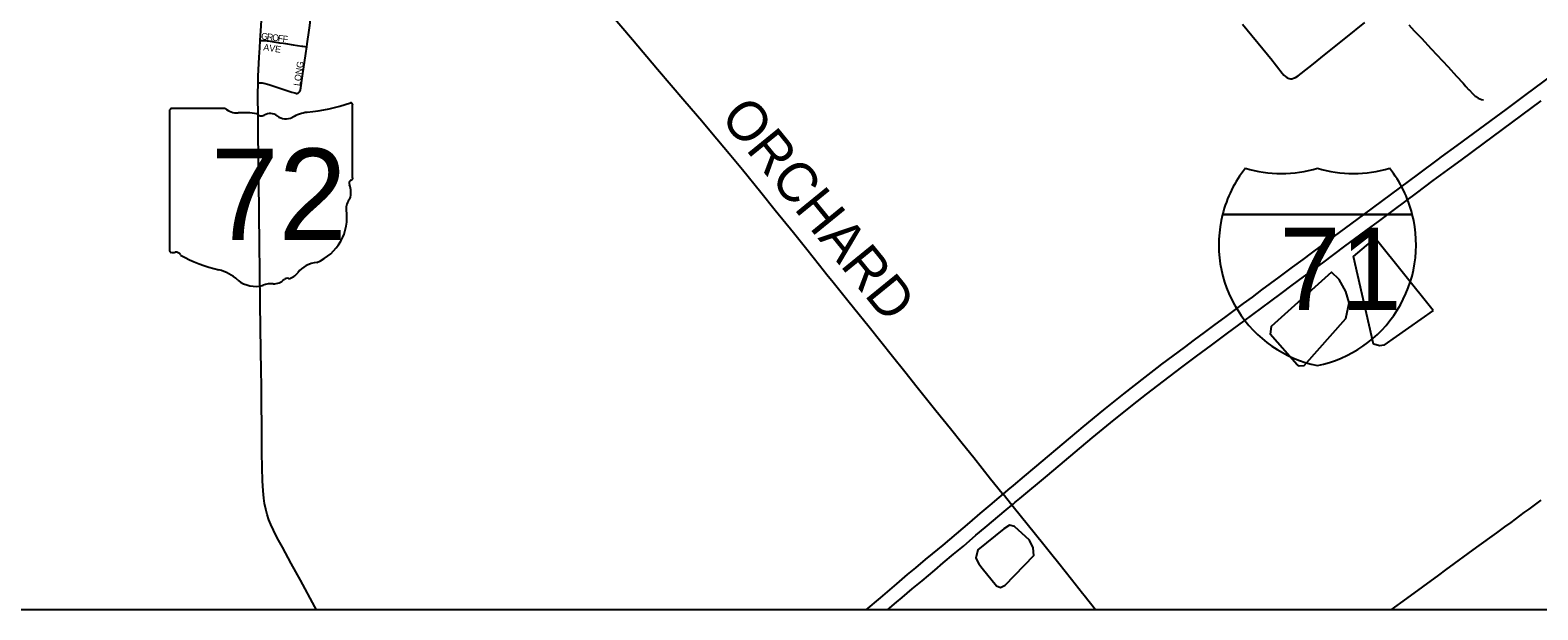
# Model space of a CAD drawing. Extents: x -49 to -8.2, y 9.4 to 23.5.
# Drawn here: x -12.253 to -11.168, y 9.409 to 9.826 of the extents above; entities that cross this region are included whole.
import ezdxf

# ---------------------------------------------------------------- set-up
doc = ezdxf.new("R2010")
doc.units = 0
for name, color, linetype in [('GM_X_Adjacent_County', 7, 'Continuous'), ('GM_X_County_Road', 7, 'Continuous'), ('GM_X_County_Road_Text', 7, 'Continuous'), ('GM_X_Interstate_Route', 7, 'Continuous'), ('GM_X_Interstate_Shield', 7, 'Continuous'), ('GM_X_Minor_Lake', 7, 'Continuous'), ('GM_X_State_Route', 7, 'Continuous'), ('GM_X_State_Shield', 7, 'Continuous'), ('GM_X_Township_Road', 7, 'Continuous'), ('GM_X_Township_Subdivision', 7, 'Continuous'), ('GM_X_Township_Subdivision_Text', 7, 'Continuous')]:
    doc.layers.add(name, color=color, linetype=linetype)

msp = doc.modelspace()

# ---------------------------------------------------------------- linework, layer by layer
at = {"layer": 'GM_X_Adjacent_County'}
msp.add_lwpolyline([(-14.9662, 16.2087), (-8.1662, 16.2087), (-8.1662, 9.4087), (-14.9662, 9.4087)], close=True, dxfattribs=at)
at = {"layer": 'GM_X_County_Road'}
for points in [[(-11.6146, 9.5686), (-11.6235, 9.5799), (-11.6324, 9.591), (-11.6493, 9.6121), (-11.6604, 9.626), (-11.6645, 9.631), (-11.6751, 9.6443), (-11.6796, 9.6498), (-11.6849, 9.6565), (-11.6942, 9.6681), (-11.7038, 9.68), (-11.7168, 9.6962), (-11.7272, 9.7091), (-11.7404, 9.7253), (-11.75, 9.7369), (-11.7628, 9.7521), (-11.7698, 9.7604), (-11.7819, 9.7745), (-11.8016, 9.7975), (-11.8197, 9.819), (-11.8462, 9.8503)], [(-11.4944, 9.419), (-11.4956, 9.4205), (-11.5035, 9.4305), (-11.5126, 9.4419), (-11.5186, 9.4494), (-11.5235, 9.4555), (-11.5354, 9.4702), (-11.5446, 9.4815), (-11.5465, 9.4839), (-11.5528, 9.4918), (-11.5533, 9.4924), (-11.5617, 9.5028), (-11.5739, 9.5181), (-11.5823, 9.5285), (-11.5907, 9.5389), (-11.6012, 9.552), (-11.6136, 9.5675), (-11.6146, 9.5686)], [(-11.4861, 9.4087), (-11.4944, 9.419)]]:
    msp.add_lwpolyline(points, dxfattribs=at)
at = {"layer": 'GM_X_Interstate_Route'}
for points in [[(-11.6513, 9.4087), (-11.6411, 9.4173), (-11.6359, 9.4217), (-11.6293, 9.4273), (-11.6215, 9.434), (-11.6155, 9.439), (-11.6086, 9.4448), (-11.6036, 9.449), (-11.596, 9.4553), (-11.5768, 9.4716), (-11.5692, 9.478), (-11.5621, 9.4841), (-11.5556, 9.4894), (-11.5528, 9.4918), (-11.549, 9.495), (-11.5452, 9.4982), (-11.5373, 9.5048), (-11.5299, 9.511), (-11.5041, 9.5328), (-11.495, 9.5404), (-11.4801, 9.5526), (-11.4659, 9.5641), (-11.4505, 9.5762), (-11.4418, 9.5828), (-11.4384, 9.5854), (-11.4222, 9.5975), (-11.415, 9.6029), (-11.4078, 9.6083), (-11.4, 9.614), (-11.393, 9.6192), (-11.3795, 9.6291), (-11.3732, 9.6337), (-11.3663, 9.6389), (-11.3538, 9.6482), (-11.3443, 9.6552), (-11.3366, 9.6609), (-11.3306, 9.6653), (-11.3231, 9.6709), (-11.2931, 9.6931), (-11.2534, 9.7224), (-11.2392, 9.733), (-11.237, 9.7347), (-11.2257, 9.7429), (-11.1977, 9.7636), (-11.1905, 9.7689), (-11.177, 9.7789), (-11.1418, 9.8051)], [(-11.636, 9.4087), (-11.6296, 9.4141), (-11.6255, 9.4175), (-11.6182, 9.4237), (-11.611, 9.4296), (-11.602, 9.4372), (-11.5958, 9.4424), (-11.5885, 9.4487), (-11.5813, 9.4546), (-11.5723, 9.4623), (-11.5656, 9.4679), (-11.5505, 9.4807), (-11.5465, 9.4839), (-11.5452, 9.485), (-11.5442, 9.4858), (-11.5406, 9.4888), (-11.5208, 9.5053), (-11.4885, 9.5325), (-11.4753, 9.5433), (-11.4595, 9.556), (-11.4495, 9.5639), (-11.4372, 9.5733), (-11.4241, 9.5833), (-11.4134, 9.5913), (-11.4027, 9.5992), (-11.3912, 9.6077), (-11.3794, 9.6164), (-11.36, 9.6308), (-11.3525, 9.6364), (-11.3445, 9.6423), (-11.3363, 9.6484), (-11.3225, 9.6585), (-11.3065, 9.6704), (-11.2958, 9.6783), (-11.2903, 9.6824), (-11.2823, 9.6883), (-11.2708, 9.6968), (-11.2549, 9.7087), (-11.2429, 9.7176), (-11.2324, 9.7253), (-11.2299, 9.7272), (-11.2229, 9.7323), (-11.2069, 9.7442), (-11.1652, 9.775)]]:
    msp.add_lwpolyline(points, dxfattribs=at)
at = {"layer": 'GM_X_Interstate_Shield'}
for p, q in [((-11.3947, 9.6933), (-11.2581, 9.6933)), ((-11.2581, 9.6933), (-11.3947, 9.6933)), ((-11.2581, 9.6933), (-11.3947, 9.6933))]:
    msp.add_line(p, q, dxfattribs=at)
for centre, start, end in [((-11.3086, 9.6715), 141.669, 165.8066), ((-11.3523, 9.8115), 253.0091, 286.9909), ((-11.3004, 9.8115), 253.0091, 286.9909), ((-11.3441, 9.6715), 14.1934, 38.331), ((-11.3086, 9.6715), 165.8066, 258.463), ((-11.3441, 9.6715), 281.537, 14.1934)]:
    msp.add_arc(centre, 0.0888, start, end, dxfattribs=at)
at = {"layer": 'GM_X_Minor_Lake'}
for points in [[(-11.2429, 9.6241), (-11.2785, 9.5992), (-11.2814, 9.5986), (-11.286, 9.6), (-11.3003, 9.6631), (-11.2848, 9.6761)], [(-11.2429, 9.6241), (-11.2848, 9.6761)], [(-11.3409, 9.5849), (-11.3396, 9.5843), (-11.3358, 9.5846), (-11.3058, 9.6183), (-11.3035, 9.6297), (-11.3059, 9.6379), (-11.3108, 9.6465), (-11.3161, 9.6517), (-11.3597, 9.6127), (-11.3605, 9.607)], [(-11.3409, 9.5849), (-11.3605, 9.607)], [(-11.5574, 9.4259), (-11.5545, 9.4247), (-11.5513, 9.4264), (-11.5307, 9.4478), (-11.531, 9.4533), (-11.5338, 9.4589), (-11.5445, 9.4687), (-11.5481, 9.4695), (-11.5522, 9.4669), (-11.571, 9.4519), (-11.5724, 9.4458), (-11.5703, 9.4418), (-11.5679, 9.4387)], [(-11.5679, 9.4387), (-11.5574, 9.4259)]]:
    msp.add_lwpolyline(points, dxfattribs=at)
at = {"layer": 'GM_X_State_Route'}
for points in [[(-12.0884, 9.8066), (-12.088, 9.8133), (-12.0877, 9.8186), (-12.087, 9.8291), (-12.0861, 9.8449), (-12.0852, 9.8578), (-12.0848, 9.862), (-12.0844, 9.8659)], [(-12.0473, 9.4087), (-12.0485, 9.4108), (-12.0588, 9.43), (-12.0655, 9.4421), (-12.0718, 9.4537), (-12.0755, 9.4605), (-12.0783, 9.4659), (-12.0802, 9.4701), (-12.0816, 9.4735), (-12.0828, 9.4773), (-12.0838, 9.4812), (-12.0846, 9.4851), (-12.0852, 9.4891), (-12.0857, 9.4943), (-12.0861, 9.5015), (-12.0864, 9.5111), (-12.0865, 9.5217), (-12.0866, 9.5387), (-12.0868, 9.5592), (-12.0869, 9.5701), (-12.0871, 9.5807), (-12.0872, 9.5953), (-12.0877, 9.6288), (-12.088, 9.6531), (-12.0882, 9.6708), (-12.0884, 9.6947), (-12.0888, 9.7171), (-12.0889, 9.7366), (-12.0892, 9.749), (-12.0893, 9.763), (-12.0894, 9.7796), (-12.0893, 9.7881), (-12.0892, 9.7928), (-12.0884, 9.8066)]]:
    msp.add_lwpolyline(points, dxfattribs=at)
at = {"layer": 'GM_X_State_Shield'}
for p, q in [((-12.153, 9.7678), (-12.153, 9.6677)), ((-12.1131, 9.7695), (-12.1517, 9.7695)), ((-12.0212, 9.7196), (-12.0212, 9.772)), ((-12.0212, 9.7197), (-12.0212, 9.7196))]:
    msp.add_line(p, q, dxfattribs=at)
for centre, radius, start, end in [((-12.0681, 9.9059), 0.1398, 275.8445, 288.9065), ((-12.0226, 9.7722), 0.00147, 351.8621, 97.738), ((-12.1515, 9.768), 0.00153, 98.1301, 188.1301), ((-12.1039, 9.7811), 0.0148, 231.6195, 271.1119), ((-12.099, 9.7133), 0.0532, 80.4867, 94.9883), ((-12.0869, 9.7685), 0.00427, 219.7921, 297.1024), ((-12.0806, 9.757), 0.00889, 54.4667, 119.1411), ((-12.0692, 9.7728), 0.0107, 233.8562, 294.8282), ((-12.0503, 9.7389), 0.0281, 97.3462, 120.7689), ((-12.0227, 9.7194), 0.00157, 289.6038, 7.7341), ((-12.0215, 9.7158), 0.00227, 107.944, 210.337), ((-12.036, 9.7092), 0.0136, 340.033, 23.6496), ((-12.0159, 9.6977), 0.00992, 136.8065, 186.9296), ((-12.0603, 9.6911), 0.035, 292.3089, 8.9858), ((-12.1515, 9.6675), 0.00154, 171.9584, 258.3066), ((-12.1512, 9.6777), 0.0118, 267.339, 280.6039), ((-12.1488, 9.662), 0.00424, 29.7484, 93.2717), ((-12.0953, 9.7519), 0.101, 240.4129, 257.1985), ((-12.1254, 9.6228), 0.0316, 47.1842, 75.836), ((-12.0455, 9.6396), 0.0192, 94.4031, 142.5768), ((-12.0912, 9.6615), 0.02, 230.7004, 286.2918), ((-12.0797, 9.6269), 0.0165, 85.6951, 111.2099), ((-12.0782, 9.654), 0.0107, 268.777, 315.5493), ((-12.0685, 9.6443), 0.00301, 65.7517, 132.6484), ((-12.0698, 9.658), 0.0113, 282.8732, 323.2771)]:
    msp.add_arc(centre, radius, start, end, dxfattribs=at)
at = {"layer": 'GM_X_Township_Road'}
for points in [[(-11.3803, 9.8302), (-11.3624, 9.8083), (-11.3614, 9.8071), (-11.36, 9.8055), (-11.3517, 9.795), (-11.3505, 9.7936), (-11.3494, 9.7925), (-11.3483, 9.7918), (-11.3475, 9.7914), (-11.3466, 9.7911), (-11.3457, 9.791), (-11.3448, 9.791), (-11.3436, 9.7913), (-11.3429, 9.7915), (-11.3422, 9.7919), (-11.3403, 9.793), (-11.338, 9.7947), (-11.3291, 9.8018), (-11.324, 9.8059), (-11.314, 9.8139), (-11.3058, 9.8205), (-11.2922, 9.8314)], [(-11.2606, 9.8298), (-11.2566, 9.8255), (-11.2515, 9.8201), (-11.2444, 9.8126), (-11.2323, 9.7995), (-11.2261, 9.7928), (-11.2215, 9.7877), (-11.2194, 9.7854), (-11.2175, 9.7833), (-11.2173, 9.7831)], [(-11.2173, 9.7831), (-11.2141, 9.7798), (-11.2127, 9.7785), (-11.2122, 9.7781), (-11.2115, 9.7776), (-11.2106, 9.777), (-11.2094, 9.7765), (-11.2081, 9.7761), (-11.2068, 9.7758)], [(-11.2732, 9.4087), (-11.262, 9.4169), (-11.2388, 9.4337), (-11.2338, 9.4374), (-11.2115, 9.4537), (-11.1972, 9.4642), (-11.1914, 9.4683), (-11.1869, 9.4716), (-11.1774, 9.4786), (-11.1739, 9.4812), (-11.1691, 9.4847), (-11.1651, 9.4876)]]:
    msp.add_lwpolyline(points, dxfattribs=at)
at = {"layer": 'GM_X_Township_Subdivision'}
for points in [[(-12.0543, 9.814), (-12.054, 9.8162), (-12.0525, 9.826), (-12.052, 9.8293), (-12.0515, 9.8338), (-12.0508, 9.839), (-12.0504, 9.8417), (-12.0499, 9.8457), (-12.0495, 9.8478), (-12.0491, 9.8515), (-12.0489, 9.853), (-12.0487, 9.8541), (-12.0486, 9.855), (-12.0485, 9.8559), (-12.0484, 9.8571), (-12.0479, 9.861)], [(-12.0877, 9.8186), (-12.0872, 9.8185), (-12.0837, 9.8184), (-12.0827, 9.8183), (-12.082, 9.8182), (-12.075, 9.8171), (-12.0738, 9.8169), (-12.0709, 9.8165), (-12.0695, 9.8163), (-12.0641, 9.8154), (-12.0577, 9.8144), (-12.057, 9.8144), (-12.0543, 9.814)], [(-12.0599, 9.781), (-12.0594, 9.7815), (-12.0592, 9.7819), (-12.059, 9.7821), (-12.0589, 9.7823), (-12.0588, 9.7827), (-12.0587, 9.7832), (-12.0585, 9.7845), (-12.0572, 9.7931), (-12.055, 9.8091), (-12.0543, 9.814)], [(-12.0893, 9.7881), (-12.0881, 9.7881), (-12.0871, 9.788), (-12.0863, 9.788), (-12.0851, 9.7877), (-12.0816, 9.7867), (-12.0737, 9.7841), (-12.0649, 9.7813), (-12.0628, 9.7807), (-12.0622, 9.7805), (-12.0618, 9.7804), (-12.0613, 9.7804), (-12.0611, 9.7804), (-12.0608, 9.7805), (-12.0604, 9.7806), (-12.0599, 9.781)]]:
    msp.add_lwpolyline(points, dxfattribs=at)

# ---------------------------------------------------------------- texts
at = {"layer": 'GM_X_County_Road_Text'}
msp.add_text('ORCHARD', height=0.02841, rotation=309.1612, dxfattribs=at).set_placement((-11.7572, 9.7629))
at = {"layer": 'GM_X_Interstate_Shield'}
msp.add_text('71', height=0.05919, dxfattribs=at).set_placement((-11.3537, 9.6245))
at = {"layer": 'GM_X_State_Shield'}
msp.add_text('72', height=0.06592, dxfattribs=at).set_placement((-12.1235, 9.6748))
at = {"layer": 'GM_X_Township_Subdivision_Text'}
for s, rotation, p in [('G', 352.1403, (-12.0873, 9.8195)), ('R', 352.1437, (-12.0832, 9.819)), ('O', 352.1461, (-12.0794, 9.8185)), ('F', 352.1327, (-12.0753, 9.8179)), ('F', 354.065, (-12.0718, 9.8174)), ('AVE', 351.383, (-12.0857, 9.8115)), ('LONG', 81.253, (-12.0591, 9.7855))]:
    msp.add_text(s, height=0.00473, rotation=rotation, dxfattribs=at).set_placement(p)

doc.saveas('drawing.dxf')
